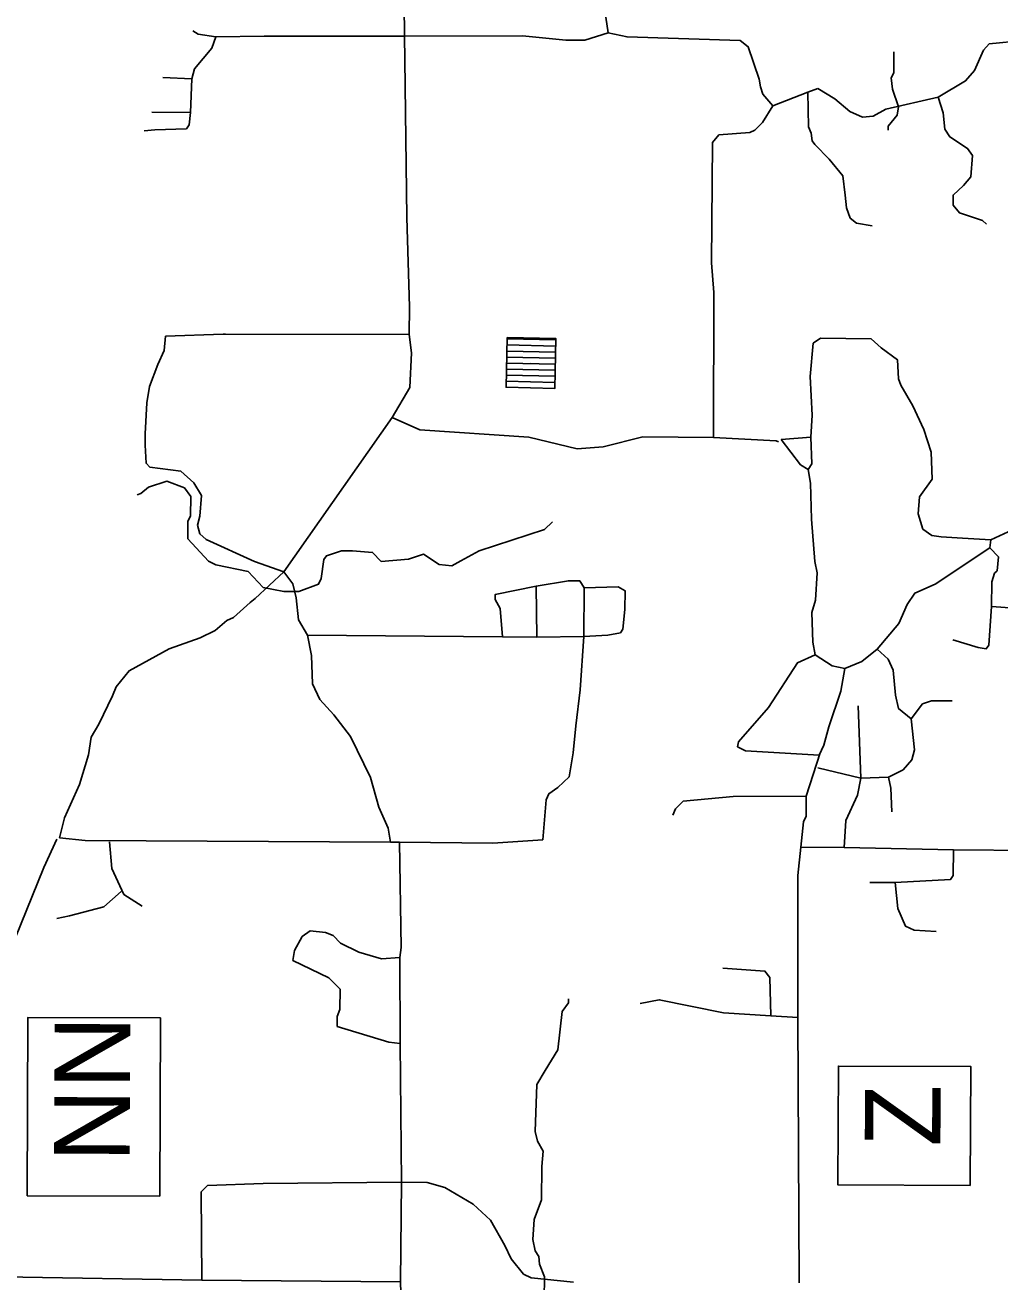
# Model space of a CAD drawing. Extents: x 299354 to 1325680, y 96128 to 228242.
# Drawn here: x 341858 to 354741, y 158651 to 175255 of the extents above; entities that cross this region are included whole.
import ezdxf

# ---------------------------------------------------------------- set-up
doc = ezdxf.new("R2010")
doc.units = 0
for name, color, linetype in [('Level 13', 7, 'Continuous'), ('Level 2', 7, 'Continuous'), ('Level 4', 7, 'Continuous'), ('Level 51', 7, 'Continuous'), ('Level 57', 7, 'Continuous')]:
    doc.layers.add(name, color=color, linetype=linetype)

msp = doc.modelspace()

# ---------------------------------------------------------------- linework, layer by layer
at = {"layer": 'Level 13'}
for p, q in [((342743, 161014), (342743, 161014)), ((353456, 160747), (353456, 160747))]:
    msp.add_line(p, q, dxfattribs=at)
for points in [[(343636, 159783), (341886, 159790), (341895, 162145), (343645, 162138)], [(354350, 159926), (352600, 159933), (352607, 161503), (354357, 161496)]]:
    msp.add_lwpolyline(points, close=True, dxfattribs=at)
at = {"layer": 'Level 2'}
for points in [[(346851, 177205), (346870, 175110)], [(346870, 175110), (346875, 174796)], [(346875, 174796), (346904, 172712)], [(346904, 172712), (346937, 171534), (346934, 171168)], [(346707, 170070), (346944, 170467), (346965, 170926), (346934, 171168)], [(345279, 168032), (346707, 170070)], [(346707, 170070), (347073, 169908), (348514, 169812), (349155, 169656), (349497, 169686), (350024, 169815), (350958, 169806)], [(350958, 169806), (351783, 169765), (351816, 169748)], [(351850, 169781), (352106, 169446), (352205, 169386)], [(352205, 169386), (352237, 169203), (352249, 168728)], [(352249, 168728), (352294, 168169), (352326, 168019), (352306, 167660), (352254, 167494), (352267, 167102), (352299, 166936)], [(354623, 168456), (354908, 168587)], [(354606, 168348), (354623, 168456)], [(353117, 167011), (353404, 167351), (353515, 167600), (353616, 167749), (353884, 167871), (354606, 168348)], [(342833, 166021), (343012, 166395), (343063, 166511), (343232, 166726), (343760, 167013), (344170, 167159), (344371, 167257), (344522, 167389), (344614, 167430), (344833, 167628), (344900, 167678), (345279, 168032)], [(352299, 166936), (352523, 166792), (352690, 166757)], [(352690, 166757), (352916, 166847), (353117, 167011)], [(352354, 165610), (352413, 165743), (352482, 165984), (352637, 166457), (352690, 166757)], [(342732, 165847), (342833, 166021)], [(342380, 164784), (342576, 165223), (342696, 165614), (342732, 165847)], [(352182, 165070), (352367, 165639)], [(352109, 164395), (352145, 164728), (352179, 164803), (352182, 165070)], [(342311, 164518), (342380, 164784)], [(341555, 163066), (341723, 163181), (342107, 164128), (342277, 164501)], [(352072, 164021), (352109, 164395)], [(352072, 164021), (352072, 162146)], [(352072, 162146), (352089, 158637)]]:
    msp.add_lwpolyline(points, dxfattribs=at)
at = {"layer": 'Level 4'}
for points in [[(349492, 178086), (349503, 175678), (349533, 175361), (349565, 175152)], [(344377, 175099), (344143, 175135), (344074, 175182)], [(344063, 174544), (344097, 174677), (344325, 174950), (344377, 175099)], [(344377, 175099), (345019, 175110), (346870, 175110)], [(346870, 175110), (348430, 175112), (349005, 175057), (349255, 175055), (349565, 175152)], [(349565, 175152), (349814, 175100), (351307, 175053), (351414, 174969), (351560, 174542), (351576, 174442), (351609, 174342), (351741, 174191)], [(353927, 174304), (354287, 174518), (354405, 174658), (354525, 174924), (354600, 175007), (355051, 175052), (357511, 174997)], [(343679, 174564), (344063, 174544)], [(344042, 174102), (344063, 174544)], [(351741, 174191), (352201, 174370)], [(352201, 174370), (352335, 174419)], [(352201, 174370), (352213, 173911), (352246, 173828), (352262, 173728), (352295, 173677), (352485, 173484), (352666, 173266), (352697, 173007), (352712, 172840), (352761, 172706), (352844, 172639), (353052, 172604)], [(352335, 174419), (352559, 174283), (352757, 174115), (352924, 174038), (353065, 174054), (353233, 174144)], [(350958, 169806), (350959, 171723), (350929, 172115), (350944, 173706), (351028, 173806), (351437, 173835), (351504, 173868), (351605, 173967), (351741, 174191)], [(353233, 174144), (353927, 174304)], [(353927, 174304), (353992, 174095), (354015, 173879), (354080, 173778), (354313, 173626), (354378, 173534), (354359, 173250), (354258, 173135), (354123, 173011), (354122, 172877), (354205, 172777), (354512, 172674), (354562, 172624)], [(343431, 173858), (343573, 173873), (343990, 173886), (344024, 173936), (344042, 174102)], [(343533, 174107), (344042, 174102)], [(343465, 170266), (343500, 170482), (343611, 170773), (343696, 170955), (343715, 171147)], [(343715, 171147), (344474, 171173), (344507, 171173), (346934, 171168)], [(352242, 169811), (352262, 170103), (352233, 170611), (352271, 171053), (352371, 171118), (353038, 171112), (353171, 170994), (353386, 170834), (353400, 170584), (353433, 170500), (353589, 170224), (353736, 169914), (353833, 169613), (353847, 169255), (353678, 169023), (353659, 168798), (353724, 168598), (353840, 168513), (353965, 168495)], [(343444, 169857), (343465, 170266)], [(343443, 169707), (343444, 169857)], [(343443, 169707), (343457, 169466), (343507, 169415), (343915, 169361), (344089, 169210), (344187, 169042), (344168, 168767), (344134, 168651), (344166, 168534), (344249, 168458), (344888, 168169), (345279, 168032)], [(351850, 169781), (352242, 169811)], [(352205, 169386), (352256, 169461), (352242, 169811)], [(353965, 168495), (354248, 168476)], [(354248, 168476), (354623, 168456)], [(354606, 168348), (354721, 168230), (354703, 168047), (354669, 168014), (354635, 167898), (354632, 167573)], [(354632, 167573), (354932, 167553), (355566, 167581), (355750, 167663), (355868, 167812), (355873, 168270)], [(345279, 168032), (345394, 167873), (345442, 167689), (345473, 167397), (345588, 167196)], [(348613, 167844), (349039, 167915), (349189, 167914), (349247, 167821)], [(348165, 167173), (348135, 167548), (348069, 167665), (348070, 167732), (348613, 167844)], [(348613, 167844), (348623, 167169)], [(349241, 167180), (349558, 167194), (349725, 167225), (349759, 167275), (349786, 167533), (349788, 167783), (349697, 167834), (349247, 167821)], [(349241, 167180), (349247, 167821)], [(354119, 167136), (354452, 167033), (354560, 167015), (354594, 167065), (354632, 167573)], [(345588, 167196), (345644, 166929), (345657, 166554), (345755, 166345), (345937, 166143), (346159, 165858), (346421, 165314), (346534, 164921), (346657, 164645), (346689, 164461)], [(345588, 167196), (348165, 167173)], [(348165, 167173), (348623, 167169)], [(348623, 167169), (349241, 167180)], [(348699, 164493), (348745, 165018), (348780, 165101), (348897, 165183), (349048, 165323), (349101, 165639), (349138, 165997), (349193, 166472), (349241, 167180)], [(351271, 165720), (351288, 165786), (351684, 166241), (352065, 166829), (352299, 166936)], [(353117, 167011), (353266, 166877), (353332, 166734), (353362, 166401), (353402, 166226), (353567, 166091)], [(352868, 166264), (352901, 165305)], [(353567, 166091), (353719, 166289), (353837, 166330), (354112, 166327)], [(353268, 165318), (353461, 165417), (353579, 165549), (353614, 165682), (353567, 166091)], [(351271, 165720), (351378, 165669), (352354, 165610)], [(352335, 165443), (352901, 165305)], [(352684, 164390), (352704, 164748), (352858, 165080), (352901, 165305)], [(352901, 165305), (353268, 165318)], [(353268, 165318), (353300, 165176), (353314, 164860)], [(350420, 164819), (350454, 164902), (350555, 165001), (351214, 165062)], [(351214, 165062), (352182, 165070)], [(342311, 164518), (342652, 164481)], [(342652, 164481), (346689, 164461)], [(342973, 164467), (343003, 164111), (343164, 163770), (343404, 163614)], [(346689, 164461), (346805, 164460)], [(346805, 164460), (346826, 163068), (346808, 162935)], [(346805, 164460), (348040, 164449)], [(348040, 164449), (348699, 164493)], [(352109, 164395), (352684, 164390)], [(352684, 164390), (354127, 164361)], [(353356, 163926), (354090, 163969), (354124, 164019), (354127, 164361)], [(354127, 164361), (357312, 164332)], [(353022, 163929), (353356, 163926)], [(353356, 163926), (353394, 163584), (353492, 163350), (353608, 163299), (353900, 163279)], [(343128, 163808), (342898, 163607), (342446, 163486), (342277, 163452)], [(346808, 162935), (346566, 162921), (346267, 163007), (346026, 163126), (345927, 163226), (345827, 163269), (345627, 163287), (345518, 163213), (345416, 163031), (345398, 162898), (345871, 162669), (346020, 162517), (346018, 162251), (345984, 162159), (345982, 162026), (346664, 161820), (346814, 161802)], [(346808, 162935), (346814, 161802)], [(351077, 162796), (351635, 162758), (351701, 162674), (351713, 162166)], [(349988, 162331), (350239, 162379), (351088, 162205), (351713, 162166)], [(351713, 162166), (352072, 162146)], [(346814, 161802), (346831, 159968)], [(344192, 158675), (344186, 159842), (344270, 159925), (345004, 159951), (346831, 159968)], [(346819, 158652), (346831, 159968)], [(346831, 159968), (347173, 159965), (347405, 159896), (347779, 159676), (348010, 159466), (348199, 159131), (348281, 158955), (348446, 158753), (348545, 158703), (349104, 158648)], [(341565, 158716), (344192, 158675)], [(344192, 158675), (346819, 158652)], [(346819, 158652), (346844, 157768), (346837, 153385)]]:
    msp.add_lwpolyline(points, dxfattribs=at)
at = {"layer": 'Level 51'}
for p, q in [((348226, 171030), (348871, 171016)), ((348228, 171110), (348873, 171096)), ((348222, 170870), (348867, 170856)), ((348224, 170950), (348869, 170936)), ((348219, 170710), (348864, 170696)), ((348221, 170790), (348866, 170776)), ((348534, 170798), (348534, 170798)), ((348216, 170550), (348860, 170536)), ((348217, 170630), (348862, 170616))]:
    msp.add_line(p, q, dxfattribs=at)
msp.add_lwpolyline([(348228, 171127), (348214, 170470), (348859, 170456), (348873, 171113)], close=True, dxfattribs=at)
at = {"layer": 'Level 57'}
for points in [[(353265, 173869), (353265, 173919), (353383, 174068), (353401, 174176), (353320, 174410), (353305, 174560), (353339, 174626), (353341, 174901)], [(343338, 169050), (343388, 169066), (343489, 169149), (343731, 169230), (343964, 169144), (344046, 169027), (344044, 168769), (344010, 168702), (344008, 168469), (344280, 168175), (344380, 168124), (344804, 168037), (345003, 167827), (345277, 167774), (345477, 167772), (345737, 167870), (345771, 167945), (345807, 168194), (345840, 168244), (346041, 168309), (346183, 168308), (346450, 168289), (346565, 168171), (346924, 168201), (347125, 168266), (347332, 168131), (347499, 168112), (347616, 168178), (347859, 168309), (348721, 168593), (348830, 168692)], [(349039, 162390), (349038, 162340), (348954, 162224), (348899, 161716), (348730, 161443), (348620, 161260), (348597, 160636), (348630, 160510), (348703, 160376), (348685, 160176), (348681, 159735), (348587, 159477), (348568, 159211), (348600, 159060), (348649, 158985), (348656, 158885), (348721, 158718), (348719, 158426)]]:
    msp.add_lwpolyline(points, dxfattribs=at)

# ---------------------------------------------------------------- texts
at = {"layer": 'Level 13'}
for s, p in [('NN', (343240, 160232)), ('Z', (353955, 160438))]:
    msp.add_text(s, height=1000, rotation=89.767, dxfattribs=at).set_placement(p)

doc.saveas('drawing.dxf')
